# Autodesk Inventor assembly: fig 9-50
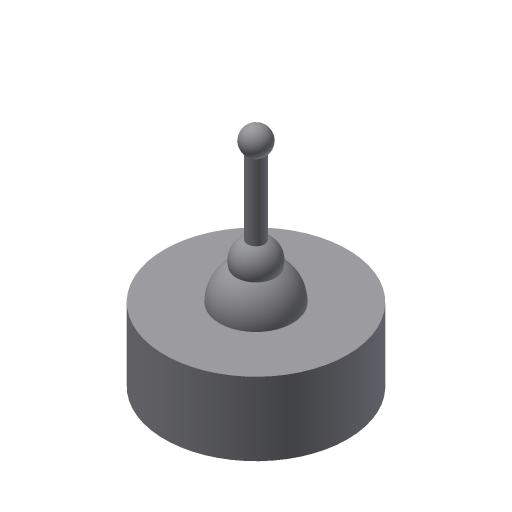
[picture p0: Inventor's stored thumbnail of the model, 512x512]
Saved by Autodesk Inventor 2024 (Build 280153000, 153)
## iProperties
Created: 2013-07
Part Number: fig 9-50
Document SubType Name: Assembly
Designer: CADCIM
Author: CADCIM
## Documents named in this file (3)
- D:\PROJECTS\Project 2023\RESOURCES INVENTOR 2024\RESOURCES INVENTOR 2024\Inventor_2023_Part\Inventor_2024_Part\c09_Inv_2024_prt\fig 9-51.iam
- D:\PROJECTS\Project 2023\RESOURCES INVENTOR 2024\RESOURCES INVENTOR 2024\Inventor_2023_Part\Inventor_2024_Part\c09_Inv_2024_prt\19.ipt
- D:\PROJECTS\Project 2023\RESOURCES INVENTOR 2024\RESOURCES INVENTOR 2024\Inventor_2023_Part\Inventor_2024_Part\c09_Inv_2024_prt\20.ipt
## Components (2 placed, 2 different names)
1. 19:1 — Ball:1
2. 20:1 — Ball:1
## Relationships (1: BallJoint 1)
- Ball:1: 19:1 ↔ 20:1
